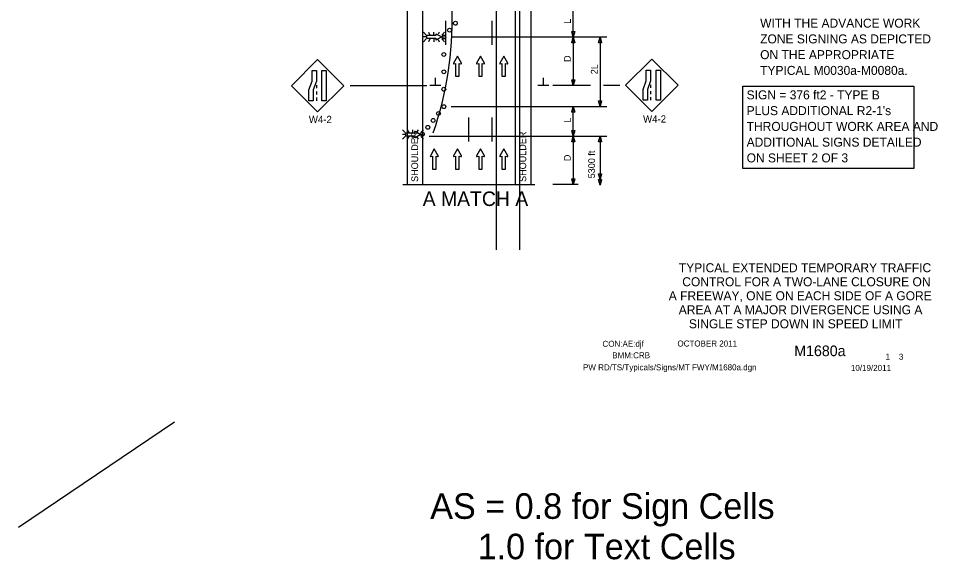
# Model space of a CAD drawing. Extents: x 16486 to 19505, y 5576 to 6998.
# Drawn here: x 16486 to 17438, y 5738 to 6298 of the extents above; entities that cross this region are included whole.
import ezdxf

# ---------------------------------------------------------------- set-up
doc = ezdxf.new("R2010")
doc.units = 0
for name, color, linetype in [('ALI_LEGAL_EX', 7, 'Continuous'), ('BORDER', 7, 'Continuous'), ('BORDER_SIGNAL_WO', 7, 'Continuous'), ('MT_SCRATCH_LEVEL_E', 7, 'Continuous'), ('PAVT_EDGE_EX', 7, 'Continuous'), ('TRAFFIC_SIGNS_PR', 7, 'Continuous'), ('TYPICAL_TEXT_DIMEN_EX', 7, 'Continuous'), ('TYPICAL_TEXT_DIMEN_PR', 7, 'Continuous')]:
    doc.layers.add(name, color=color, linetype=linetype)

msp = doc.modelspace()

# ---------------------------------------------------------------- linework, layer by layer
at = {"layer": 'ALI_LEGAL_EX'}
for p, q in [((16980.68, 6974.12), (16980.68, 6155.98)), ((17004.68, 6974.12), (17004.68, 6155.98)), ((16980.68, 6922.21), (16980.68, 6058.3)), ((17004.68, 6922.21), (17004.68, 6058.3))]:
    msp.add_line(p, q, dxfattribs=at)
for points in [[(16928.4, 6270.33), (16928.4, 6295.33)], [(16976.4, 6270.33), (16976.4, 6295.33)], [(16952.4, 6170.33), (16952.4, 6195.33)], [(16976.4, 6170.33), (16976.4, 6195.33)]]:
    msp.add_lwpolyline(points, dxfattribs=at)
msp.add_arc((16571.06, 6296.99), 364, 341.14744, 21.33821, dxfattribs=at)
at = {"layer": 'MT_SCRATCH_LEVEL_E'}
for p, q in [((16940.5, 6258.7), (16936.39, 6251.46)), ((16944.64, 6251.46), (16940.5, 6258.7)), ((16964.4, 6258.7), (16960.29, 6251.46)), ((16968.55, 6251.46), (16964.4, 6258.7)), ((16988.45, 6258.7), (16984.34, 6251.46)), ((16992.6, 6251.46), (16988.45, 6258.7)), ((16936.87, 6250.78), (16938.64, 6251.09)), ((16938.64, 6251.09), (16938.64, 6237.84)), ((16942.39, 6237.84), (16942.39, 6251.09)), ((16942.39, 6251.09), (16944.16, 6250.78)), ((16960.77, 6250.78), (16962.55, 6251.09)), ((16962.55, 6251.09), (16962.55, 6237.84)), ((16966.29, 6237.84), (16966.29, 6251.09)), ((16966.29, 6251.09), (16968.07, 6250.78)), ((16984.82, 6250.78), (16986.6, 6251.09)), ((16986.6, 6251.09), (16986.6, 6237.84)), ((16990.34, 6237.84), (16990.34, 6251.09)), ((16990.34, 6251.09), (16992.12, 6250.78)), ((16938.64, 6237.84), (16942.39, 6237.84)), ((16962.55, 6237.84), (16966.29, 6237.84)), ((16986.6, 6237.84), (16990.34, 6237.84)), ((16916.59, 6162.72), (16912.48, 6155.48)), ((16920.74, 6155.48), (16916.59, 6162.72)), ((16940.5, 6162.72), (16936.39, 6155.48)), ((16944.64, 6155.48), (16940.5, 6162.72)), ((16964.4, 6162.72), (16960.29, 6155.48)), ((16968.55, 6155.48), (16964.4, 6162.72)), ((16988.45, 6162.72), (16984.34, 6155.48)), ((16992.6, 6155.48), (16988.45, 6162.72)), ((16912.96, 6154.79), (16914.74, 6155.11)), ((16914.74, 6155.11), (16914.74, 6141.85)), ((16918.48, 6141.85), (16918.48, 6155.11)), ((16918.48, 6155.11), (16920.26, 6154.79)), ((16936.87, 6154.79), (16938.64, 6155.11)), ((16938.64, 6155.11), (16938.64, 6141.85)), ((16942.39, 6141.85), (16942.39, 6155.11)), ((16942.39, 6155.11), (16944.16, 6154.79)), ((16960.77, 6154.79), (16962.55, 6155.11)), ((16962.55, 6155.11), (16962.55, 6141.85)), ((16966.29, 6141.85), (16966.29, 6155.11)), ((16966.29, 6155.11), (16968.07, 6154.79)), ((16984.82, 6154.79), (16986.6, 6155.11)), ((16986.6, 6155.11), (16986.6, 6141.85)), ((16990.34, 6141.85), (16990.34, 6155.11)), ((16990.34, 6155.11), (16992.12, 6154.79)), ((16914.74, 6141.85), (16918.48, 6141.85)), ((16938.64, 6141.85), (16942.39, 6141.85)), ((16962.55, 6141.85), (16966.29, 6141.85)), ((16986.6, 6141.85), (16990.34, 6141.85))]:
    msp.add_line(p, q, dxfattribs=at)
for centre, start, end in [((16936.79, 6251.24), 150.42484, 279.96381), ((16944.23, 6251.24), 260.03619, 29.77312), ((16960.7, 6251.24), 150.42484, 279.96381), ((16968.14, 6251.24), 260.03619, 29.77312), ((16984.75, 6251.24), 150.42484, 279.96381), ((16992.19, 6251.24), 260.03619, 29.77312), ((16912.89, 6155.25), 150.42484, 279.96381), ((16920.33, 6155.25), 260.03619, 29.77312), ((16936.79, 6155.25), 150.42484, 279.96381), ((16944.23, 6155.25), 260.03619, 29.77312), ((16960.7, 6155.25), 150.42484, 279.96381), ((16968.14, 6155.25), 260.03619, 29.77312), ((16984.75, 6155.25), 150.42484, 279.96381), ((16992.19, 6155.25), 260.03619, 29.77312)]:
    msp.add_arc(centre, 0.463, start, end, dxfattribs=at)
at = {"layer": 'PAVT_EDGE_EX'}
for p, q in [((16888.4, 6480.53), (16888.4, 6125.9)), ((16904.4, 6480.53), (16904.4, 6125.9)), ((17000.4, 6480.53), (17000.4, 6125.9)), ((17016.4, 6480.53), (17016.4, 6125.9))]:
    msp.add_line(p, q, dxfattribs=at)
at = {"layer": 'TRAFFIC_SIGNS_PR'}
for p, q in [((16908.17, 6280.57), (16905.35, 6283.39)), ((16910.47, 6283.39), (16912.1, 6280.57)), ((16916.26, 6280.57), (16916.26, 6283.39)), ((16921.73, 6283.39), (16920.52, 6281.3)), ((16927.16, 6283.39), (16924.35, 6280.57)), ((16908.17, 6278.54), (16905.35, 6278.54)), ((16908.17, 6276.51), (16905.35, 6273.69)), ((16912.12, 6276.51), (16910.5, 6273.69)), ((16916.26, 6276.51), (16916.26, 6273.69)), ((16920.44, 6275.87), (16921.7, 6273.69)), ((16924.35, 6278.54), (16927.16, 6278.54)), ((16927.16, 6273.69), (16924.35, 6276.51)), ((16795.76, 6255.3), (16768.61, 6228.14)), ((16822.91, 6228.14), (16795.76, 6255.3)), ((17141.78, 6255.72), (17114.62, 6228.57)), ((17168.93, 6228.57), (17141.78, 6255.72)), ((16768.61, 6228.14), (16795.76, 6200.99)), ((16794.51, 6228.64), (16794.51, 6225.44)), ((16795.76, 6200.99), (16822.91, 6228.14)), ((17114.62, 6228.57), (17141.78, 6201.41)), ((17140.53, 6229.06), (17140.53, 6225.86)), ((17141.78, 6201.41), (17168.93, 6228.57)), ((16794.51, 6222.24), (16794.51, 6219.04)), ((16794.51, 6215.84), (16794.51, 6212.64)), ((17140.53, 6222.66), (17140.53, 6219.46)), ((17140.53, 6216.26), (17140.53, 6213.06)), ((16886.3, 6179.62), (16883.48, 6182.44)), ((16886.3, 6177.59), (16883.48, 6177.59)), ((16888.6, 6182.44), (16890.23, 6179.62)), ((16894.39, 6179.62), (16894.39, 6182.44)), ((16899.86, 6182.44), (16898.65, 6180.35)), ((16905.29, 6182.44), (16902.47, 6179.62)), ((16902.47, 6177.59), (16905.29, 6177.59)), ((16886.3, 6175.56), (16883.48, 6172.74)), ((16890.25, 6175.56), (16888.62, 6172.74)), ((16894.39, 6175.56), (16894.39, 6172.74)), ((16898.57, 6174.92), (16899.83, 6172.74)), ((16905.29, 6172.74), (16902.47, 6175.56))]:
    msp.add_line(p, q, dxfattribs=at)
for points in [[(16918.09, 6281.22), (16918.32, 6279.93), (16908.59, 6279.93), (16908.59, 6277.18), (16918.32, 6277.18), (16918.08, 6275.88)], [(16918.59, 6275.53), (16923.9, 6278.54), (16918.59, 6281.58)], [(16896.21, 6180.27), (16896.44, 6178.97), (16886.72, 6178.97), (16886.72, 6176.23), (16896.44, 6176.23), (16896.21, 6174.93)], [(16896.71, 6174.57), (16902.02, 6177.59), (16896.71, 6180.63)]]:
    msp.add_lwpolyline(points, dxfattribs=at)
for points in [[(16794.51, 6243.88), (16794.51, 6232.7), (16791.17, 6223.82), (16791.17, 6212.64), (16786.67, 6212.64), (16786.67, 6223.82), (16790.02, 6232.7), (16790.02, 6243.88)], [(16804.65, 6243.88), (16804.65, 6212.64), (16800.15, 6212.64), (16800.15, 6243.88)], [(17140.53, 6244.3), (17140.53, 6233.12), (17137.19, 6224.24), (17137.19, 6213.06), (17132.69, 6213.06), (17132.69, 6224.24), (17136.04, 6233.12), (17136.04, 6244.3)], [(17150.67, 6244.3), (17150.67, 6213.06), (17146.17, 6213.06), (17146.17, 6244.3)]]:
    msp.add_lwpolyline(points, close=True, dxfattribs=at)
for centre in [(16938.4, 6292.75), (16932.4, 6285.61), (16926.4, 6278.47), (16926.4, 6260.47), (16926.4, 6242.47), (16926.4, 6224.47), (16926.4, 6206.47), (16920.9, 6199.34), (16909.91, 6185.08), (16915.4, 6192.21), (16904.41, 6177.96)]:
    msp.add_circle(centre, 2, dxfattribs=at)
for centre, start, end in [((16918.42, 6281.28), 61.48329, 189.95933), ((16918.42, 6275.82), 170.73078, 298.89165), ((16896.55, 6180.33), 61.48329, 189.95933), ((16896.55, 6174.87), 170.73078, 298.89165)]:
    msp.add_arc(centre, 0.341, start, end, dxfattribs=at)
at = {"layer": 'TYPICAL_TEXT_DIMEN_EX'}
msp.add_lwpolyline([(17235.9, 6227.83), (17413.17, 6227.83), (17413.17, 6142.51), (17235.9, 6142.51)], close=True, dxfattribs=at)
at = {"layer": 'TYPICAL_TEXT_DIMEN_PR'}
for p, q in [((17060.4, 6278.47), (17060.4, 6307.03)), ((17060.4, 6278.47), (17058.83, 6284.33)), ((17058.83, 6284.33), (17060.4, 6284.33)), ((17060.4, 6284.33), (17061.97, 6284.33)), ((17061.97, 6284.33), (17060.4, 6278.47)), ((17095.19, 6278.47), (16933.9, 6278.47)), ((17058.83, 6272.61), (17060.4, 6278.47)), ((17060.4, 6272.61), (17058.83, 6272.61)), ((17060.4, 6278.47), (17060.4, 6228.47)), ((17060.4, 6278.47), (17061.97, 6272.61)), ((17061.97, 6272.61), (17060.4, 6272.61)), ((17086.64, 6272.61), (17088.21, 6278.47)), ((17088.21, 6272.61), (17086.64, 6272.61)), ((17088.21, 6278.47), (17089.78, 6272.61)), ((17088.21, 6278.47), (17088.21, 6206.47)), ((17089.78, 6272.61), (17088.21, 6272.61)), ((16917.69, 6228.47), (16917.69, 6236.25)), ((17029.53, 6228.47), (17029.53, 6236.25)), ((17060.4, 6228.47), (17058.83, 6234.33)), ((17058.83, 6234.33), (17060.4, 6234.33)), ((17060.4, 6234.33), (17061.97, 6234.33)), ((17061.97, 6234.33), (17060.4, 6228.47)), ((16829.5, 6228.47), (16908.69, 6228.47)), ((16923.31, 6228.47), (16912.06, 6228.47)), ((17035.15, 6228.47), (17023.9, 6228.47)), ((17078.18, 6228.47), (17039.4, 6228.47)), ((17108.81, 6228.47), (17091.83, 6228.47)), ((16933.9, 6206.47), (17095.19, 6206.47)), ((17058.83, 6200.61), (17060.4, 6206.47)), ((17060.4, 6175.9), (17060.4, 6206.47)), ((17060.4, 6206.47), (17061.97, 6200.61)), ((17088.21, 6206.47), (17086.64, 6212.33)), ((17086.64, 6212.33), (17088.21, 6212.33)), ((17088.21, 6212.33), (17089.78, 6212.33)), ((17089.78, 6212.33), (17088.21, 6206.47)), ((17060.4, 6200.61), (17058.83, 6200.61)), ((17061.97, 6200.61), (17060.4, 6200.61)), ((17060.4, 6175.9), (17058.83, 6181.77)), ((17058.83, 6181.77), (17060.4, 6181.77)), ((17060.4, 6181.77), (17061.97, 6181.77)), ((17061.97, 6181.77), (17060.4, 6175.9)), ((16911.36, 6175.9), (17095.19, 6175.9)), ((17058.83, 6170.04), (17060.4, 6175.9)), ((17060.4, 6170.04), (17058.83, 6170.04)), ((17060.4, 6175.9), (17060.4, 6125.9)), ((17060.4, 6175.9), (17061.97, 6170.04)), ((17061.97, 6170.04), (17060.4, 6170.04)), ((17086.64, 6170.04), (17088.21, 6175.9)), ((17088.21, 6170.04), (17086.64, 6170.04)), ((17088.21, 6175.9), (17088.21, 6125.9)), ((17088.21, 6175.9), (17089.78, 6170.04)), ((17089.78, 6170.04), (17088.21, 6170.04)), ((17060.4, 6125.9), (17058.83, 6131.77)), ((17058.83, 6131.77), (17060.4, 6131.77)), ((17060.4, 6131.77), (17061.97, 6131.77)), ((17061.97, 6131.77), (17060.4, 6125.9)), ((17088.21, 6131.1), (17086.64, 6136.97)), ((17086.64, 6136.97), (17088.21, 6136.97)), ((17088.21, 6125.33), (17086.64, 6131.19)), ((17086.64, 6131.19), (17088.21, 6131.19)), ((17088.21, 6136.97), (17089.78, 6136.97)), ((17089.78, 6136.97), (17088.21, 6131.1)), ((17088.21, 6131.19), (17089.78, 6131.19)), ((17089.78, 6131.19), (17088.21, 6125.33)), ((16884.1, 6125.9), (17020.75, 6125.9)), ((17065.4, 6125.9), (17039.4, 6125.9)), ((16647.75, 5880), (16485.98, 5771.23))]:
    msp.add_line(p, q, dxfattribs=at)

# ---------------------------------------------------------------- texts
at = {"layer": 'BORDER'}
for s, p in [('TYPICAL EXTENDED TEMPORARY TRAFFIC', (17169.78, 6035.19)), ('CONTROL FOR A TWO-LANE CLOSURE ON', (17173.28, 6020.7)), ('A FREEWAY, ONE ON EACH SIDE OF A GORE', (17159.3, 6006.21)), ('AREA AT A MAJOR DIVERGENCE USING A', (17169.66, 5991.71)), ('SINGLE STEP DOWN IN SPEED LIMIT', (17180.16, 5977.22))]:
    msp.add_text(s, height=9.3, dxfattribs=at).set_placement(p)
at = {"layer": 'BORDER_SIGNAL_WO'}
for s, height, p in [('CON:AE:djf  ', 6.2, (17090.69, 5958.06)), ('    OCTOBER 2011    ', 6.2, (17159.08, 5958.34)), ('    M1680a   ', 11, (17272.86, 5948.38)), ('BMM:CRB   ', 6.2, (17100.81, 5946.17)), (' 1    3 ', 6.2, (17381.45, 5944.7)), ('PW RD/TS/Typicals/Signs/MT FWY/M1680a.dgn      ', 6.2, (17070.55, 5933.71)), ('10/19/2011    ', 6.2, (17347.93, 5933.13)), ('AS = 0.8 for Sign Cells', 26.4241, (16912.35, 5780.08)), ('     1.0 for Text Cells', 26.4241, (16912.35, 5738.29))]:
    msp.add_text(s, height=height, dxfattribs=at).set_placement(p)
at = {"layer": 'TRAFFIC_SIGNS_PR'}
for p in [(16786.72, 6189.55), (17132.73, 6189.98)]:
    msp.add_text('W4-2', height=7.44, dxfattribs=at).set_placement(p)
at = {"layer": 'TYPICAL_TEXT_DIMEN_EX'}
for s, p in [('WITH THE ADVANCE WORK', (17253.92, 6288.21)), ('ZONE SIGNING AS DEPICTED', (17253.92, 6271.91)), ('ON THE APPROPRIATE', (17253.92, 6255.61)), ('TYPICAL M0030a-M0080a.', (17253.92, 6239.31)), ('SIGN = 376 ft2 - TYPE B', (17239.95, 6214)), ("PLUS ADDITIONAL R2-1's", (17239.95, 6197.7)), ('THROUGHOUT WORK AREA AND', (17239.95, 6181.4)), ('ADDITIONAL SIGNS DETAILED', (17239.95, 6165.1)), ('ON SHEET 2 OF 3', (17239.95, 6148.8))]:
    msp.add_text(s, height=9.3, dxfattribs=at).set_placement(p)
at = {"layer": 'TYPICAL_TEXT_DIMEN_PR'}
for s, p in [('L', (17057.93, 6292.11)), ('D', (17057.84, 6252.69)), ('2L', (17085.65, 6239.97)), ('L', (17057.84, 6189.76)), ('SHOULDER', (16899.84, 6128.61)), ('SHOULDER', (17011.7, 6128.61)), ('5300 ft', (17082.9, 6132.33)), ('D', (17057.84, 6150.12))]:
    msp.add_text(s, height=7, rotation=90, dxfattribs=at).set_placement(p)
msp.add_text('A MATCH A', height=15, dxfattribs=at).set_placement((16904.56, 6103.71))

doc.saveas('drawing.dxf')
